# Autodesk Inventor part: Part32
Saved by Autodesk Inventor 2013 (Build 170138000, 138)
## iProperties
Created: 2012-07
Part Number: Part32
Material: Acetal Resin, Black
Document SubType Name: Modeling
Designer: Paul
Density: 1 g/cm^3
Author: Paul
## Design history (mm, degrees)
node "User Library-Arduino Mega.SAT1"
body "Solid1"
node "Base1"
